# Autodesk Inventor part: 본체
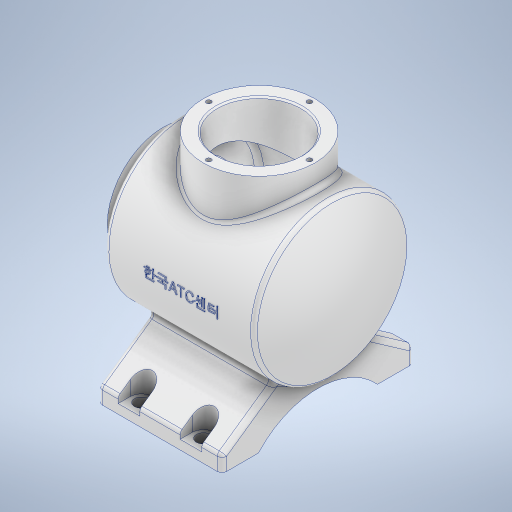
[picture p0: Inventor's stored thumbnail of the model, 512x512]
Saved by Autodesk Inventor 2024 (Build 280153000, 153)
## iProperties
Created: 2023-08
Part Number: 본체
Material: 알루미늄 6061
Document SubType Name: Modeling
Designer: Owner
Density: 2.7 g/cm^3
Appearance: 알루미늄 - 평지
Mass: 1296.71 g
Surface Area: 1060.45 cm^2
Volume: 480.264 cm^3
Author: Owner
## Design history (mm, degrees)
sketch "스케치1"
  geometry: L1 (-60, 0)-(60, 0); L2 (-48, 50)-(48.336, 50); L3 (-60, 0)-(-60, 36); L4 (-48, 36)-(-48, 50); L5 (-60, 36)-(-48, 36); A1 r 113 centre (-53, 0) between (60, 0) and (48.336, 50); 2 further points
  constraints: 12 end point, 3 horizontal, 2 point on circle, 2 vertical, 1 centre point, 1 coincident, 1 midpoint, 1 point on line
  dimensions: "d1" = 100 diameter of L2 L1; "d4" = 72 diameter of L5 L1; "d5" = 120 horizontal distance of L1.end L3.end; "d6" = 108 horizontal distance of L1.end L2.start; "d9" = 113 radius of A1
revolve "회전1" sketch "스케치1" stored, may be unused: angle "d10" = 90 deg
node "작업 평면1"
sketch "스케치2"
  geometry: L1 (60, 36)-(60, -36) reference; C1 r 36 at (-2, 0); 1 further point
  constraints: 1 centre point, 1 horizontal alignment
  dimensions: "d12" = 72 diameter of C1; "d13" = 62 distance from line of C1.centre L1
extrude "돌출1" join sketch "스케치2" stored distance "d14" = 10; taper "d15" = 0 deg
sketch "스케치4"
  geometry: L1 (-60, 27)-(-41, 27); L2 (-60, 0)-(-60, 27); L3 (-60, 0)-(53, 0); L4 (-60, -36)-(-60, 36) reference; L5 (-41, 27)-(-41, 43); L6 (-48, 50)-(48.336, 50) reference; L7 (-41, 43)-(43.887, 43); A1 r 113 centre (-53, 0) between (48.336, -50) and (48.336, 50) reference; A2 r 106 centre (-53, 0) between (53, 0) and (43.887, 43); 2 further points
  constraints: 10 end point, 2 point on circle, 2 vertical, 1 centre point, 1 horizontal, 1 horizontal alignment, 1 midpoint, 1 parallel, 1 point on line
  dimensions: "d31" = 19 distance of L1.start L1.end; "d32" = 54 diameter of L1 L3; "d34" = 7 distance between parallel lines of L6 L7; "d35" = 7 radial gap between concentric circles of A1 A2
revolve "회전3" sketch "스케치4" stored, may be unused: angle "d36" = 90 deg
sketch "스케치5"
  geometry: C1 r 36 at (0, 0) reference; C2 r 27 at (0, 0); 1 further point
  constraints: 1 centre point, 1 coincident
  dimensions: "d37" = 54 diameter of C2
extrude "돌출2" cut sketch "스케치5" stored distance "d38" = 10; taper "d39" = 0 deg
node "작업 평면5"
  node "작업 평면4"
sketch "스케치6"
  geometry: L1 (-67, -62)-(-77, -62); L2 (-77, 62)-(-67, 62); L3 (-77, -62)-(-77, -38.5); L4 (-77, 38.5)-(-77, 62); L5 (-67, -62)-(-42.278, -26.694); L6 (-67, 62)-(-42.278, 26.694); A1 r 52.096 centre (-112.096, 0) between (-77, -38.5) and (-77, 38.5); A2 r 50 centre (0, 0) between (-42.278, -26.694) and (-42.278, 26.694) reference; 3 further points
  constraints: 12 end point, 5 point on circle, 2 equal length, 2 horizontal, 1 centre point, 1 collinear, 1 horizontal alignment, 1 midpoint, 1 vertical, 1 vertical alignment
  dimensions: "d42" = 77 distance of L4.start L3.end; "d43" = 10 distance of L2.start L2.end; "d44" = 77 distance from line of point (0, 0) L4; "d45" = 17 horizontal distance of L4.start point (-60, 0); "d46" = 55 deg angle of L6 L2; "d78" = 124 vertical distance of L2.start point (-72, -62)
extrude "돌출3" join sketch "스케치6" stored distance "d47" = 80; taper "d48" = 0 deg
sketch "스케치8"
  geometry: 2 further points
  constraints: 1 vertical alignment
  dimensions: "d49" = 32.5 distance of point (0, 0) point (0, 32.5)
hole "구멍1" sketch "스케치8" at (0, 32.5) diameter "d50" = 3.242; stored, may be unused: countersink angle "d54" = 90 deg, drill point angle "d56" = 118 deg; dims "d51" = 8, "d52" = 4, "d53" = 2, "d55" = 10
sketch "스케치9"
  geometry: C1 r 27 at (0, 0) reference; 2 further points
  constraints: 1 vertical alignment
  dimensions: "d60" = 32.5 distance of C1.centre point (0, 32.5)
hole "구멍2" sketch "스케치9" at (0, 32.5) diameter "d61" = 3.242; stored, may be unused: countersink angle "d65" = 90 deg, drill point angle "d67" = 118 deg; dims "d62" = 8, "d63" = 4, "d64" = 2, "d66" = 10
node "작업 평면7"
  node "작업 평면6"
sketch "스케치10"
  geometry: L1 (40, -62)-(-40, -62) reference; L2 (-40, -38.5)-(-40, 38.5) reference; L3 (-27, -54)-(-27, -62); L4 (-13, -54)-(-13, -62); A1 r 7 centre (-20, -54) between (-13, -54) and (-27, -54); 1 further point
  constraints: 4 end point, 2 perpendicular, 2 point on circle, 2 point on line, 2 tangent, 1 centre point
  dimensions: "d73" = 14 diameter of A1; "d74" = 8 distance from line of A1.centre L1; "d75" = 20 distance from line of A1.centre L2
extrude "돌출4" cut sketch "스케치10" distance "d76" = 22; taper "d77" = 0 deg
sketch "스케치11"
  geometry: 1 further point
sketch "스케치12"
  geometry: C1 r 4.5 at (20, 54); A1 r 7 centre (20, 54) between (13, 54) and (27, 54) reference; 1 further point
  constraints: 1 centre point, 1 concentric
  dimensions: "d79" = 9 diameter of C1
extrude "돌출5" cut sketch "스케치12" extent not by distance; stored distance "d80" = 0; taper "d81" = 0 deg
fillet "모깎기1" dims "d85" = 3
fillet "모깎기2" dims "d86" = 3
fillet "모깎기3" dims "d87" = 3
fillet "모깎기4" dims "d88" = 3
node "작업 평면8"
sketch "스케치13"
  geometry: L1 (-60.168, -36)-(-60.168, 36) reference; 2 further points
  constraints: 1 horizontal alignment, 1 other
  dimensions: "d89" = 62 distance from line of point (1.832, 0) L1
feature "엠보싱1" sketch "스케치13" dims "d31" = 19, "d32" = 54, "d34" = 7, "d35" = 7, "d90" = 0.5, "d91" = 0
chamfer "모따기1" distance "d92" = 1; stored, may be unused: second distance "d93" = 2, angle "d94" = 45 deg
feature "̙耀̛耀̝耀̟耀̡耀̣耀̥耀̧耀" dims "d1" = 100, "d4" = 72, "d5" = 120, "d6" = 108, "d9" = 113, "d10" = 90 deg, "d11" = 65, "d12" = 72, "d13" = 62, "d14" = 10, "d15" = 0, "d31" = 19, "d32" = 54, "d34" = 7, "d35" = 7, "d36" = 90 deg, "d37" = 54, "d38" = 10, "d39" = 0, "d40" = -60, "d41" = 60, "d42" = 77, "d43" = 10, "d44" = 77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
node "솔리드1"
pattern_circular "원형 패턴1" dims angle "d58" = 360 deg
pattern_circular "원형 패턴2" dims angle "d69" = 360 deg
pattern_linear "직사각형 패턴1" dims "d84" = 40
mirror "미러1"
feature "A9D066F2-1C7D-4E18-AEED-F7BC21143FA4" dims "d50" = 3.242, "d51" = 8, "d52" = 4, "d53" = 2, "d54" = 90 deg, "d55" = 10, "d56" = 118 deg
